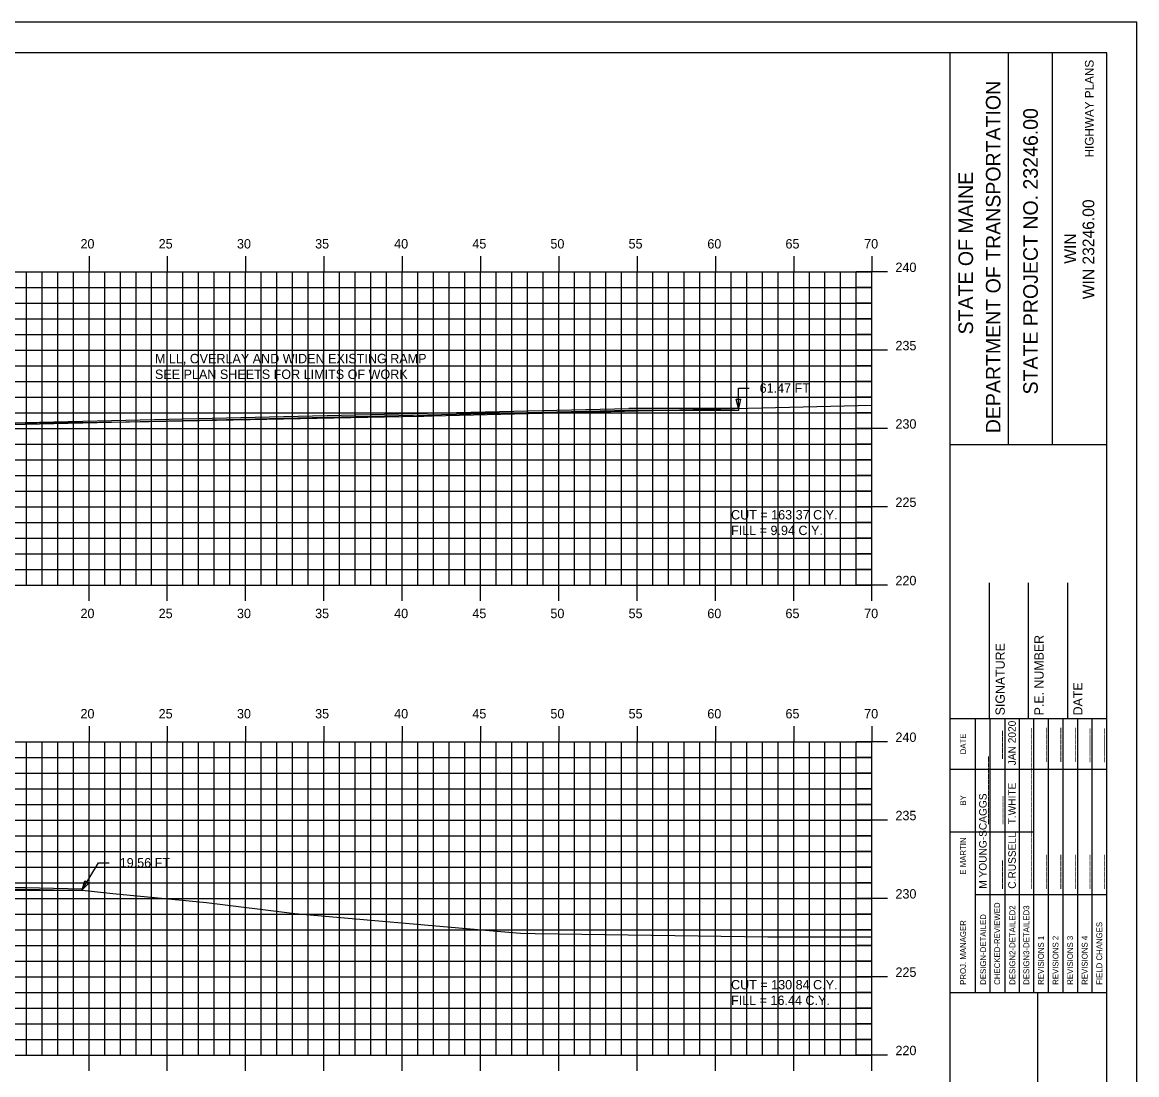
# Model space of a CAD drawing. Extents: x 1136989 to 1137159, y 608981 to 609091.
# Drawn here: x 1137087.9 to 1137159, y 609024.1 to 609091.3 of the extents above; entities that cross this region are included whole.
import ezdxf

# ---------------------------------------------------------------- set-up
doc = ezdxf.new("R2010")
doc.units = 0
for name, color, linetype in [('ANNOTATION', 7, 'Continuous'), ('BORDER', 7, 'Continuous'), ('D_Roadway_Edge_Shoulder', 7, 'Continuous'), ('D_Text_Standard', 7, 'Continuous'), ('H_V ANNOTATION', 7, 'Continuous'), ('HIGHWAY_TITLE', 7, 'Continuous'), ('MAJOR', 7, 'Continuous'), ('MINOR', 7, 'Continuous'), ('PLOT BOUNDARY', 7, 'Continuous'), ('S_Roadway_Centerline', 7, 'Continuous')]:
    doc.layers.add(name, color=color, linetype=linetype)

msp = doc.modelspace()

# ---------------------------------------------------------------- linework, layer by layer
at = {"layer": 'BORDER'}
for p, q in [((1137147.14, 608984.335), (1137147.14, 609089.335)), ((1137150.869, 609064.332), (1137150.869, 609089.332)), ((1137153.664, 609064.332), (1137153.664, 609089.332)), ((1137147.141, 609064.329), (1137157.14, 609064.329)), ((1137149.64, 609046.838), (1137149.64, 609055.485)), ((1137152.14, 609046.838), (1137152.14, 609055.485)), ((1137154.64, 609046.838), (1137154.64, 609055.485)), ((1137147.14, 609046.838), (1137157.14, 609046.838)), ((1137147.14, 609029.338), (1137157.14, 609029.338)), ((1137152.731, 608994.338), (1137152.731, 609029.338))]:
    msp.add_line(p, q, dxfattribs=at)
msp.add_lwpolyline([(1136997.14, 608984.335), (1137157.14, 608984.335), (1137157.14, 609089.335), (1136997.14, 609089.335)], close=True, dxfattribs=at)
for points in [[(1137148.755, 609043.588), (1137148.755, 609046.838)], [(1137149.687, 609029.341), (1137149.687, 609046.838)], [(1137150.619, 609046.838), (1137150.619, 609029.341)], [(1137151.551, 609029.341), (1137151.551, 609046.838)], [(1137152.482, 609029.341), (1137152.482, 609046.838)], [(1137153.414, 609029.341), (1137153.414, 609046.838)], [(1137154.346, 609029.341), (1137154.346, 609046.838)], [(1137155.278, 609029.341), (1137155.278, 609046.838)], [(1137156.209, 609029.341), (1137156.209, 609046.838)], [(1137148.756, 609029.341), (1137148.756, 609046.132)], [(1137147.14, 609043.588), (1137157.14, 609043.588)], [(1137147.14, 609039.588), (1137148.756, 609039.588)], [(1137148.755, 609039.588), (1137152.482, 609039.588)], [(1137148.755, 609035.588), (1137157.14, 609035.588)]]:
    msp.add_lwpolyline(points, dxfattribs=at)
at = {"layer": 'D_Roadway_Edge_Shoulder'}
for p in [(1137087.14, 609065.695), (1137133.61, 609066.625)]:
    msp.add_line(p, (1137126.61, 609066.625), dxfattribs=at)
for points in [[(1137133.61, 609066.625), (1137133.61, 609066.5), (1137126.61, 609066.5), (1137087.14, 609065.57)], [(1137087.14, 609036.052), (1137091.698, 609035.961), (1137091.695, 609035.836), (1137087.14, 609035.927)]]:
    msp.add_lwpolyline(points, dxfattribs=at)
at = {"layer": 'D_Text_Standard'}
for points in [[(1137133.61, 609066.625), (1137133.607, 609067.925), (1137134.287, 609067.925)], [(1137091.697, 609035.899), (1137092.74, 609037.623), (1137093.42, 609037.623)]]:
    msp.add_lwpolyline(points, dxfattribs=at)
for points in [[(1137133.61, 609066.625), (1137133.463, 609067.207), (1137133.754, 609067.208)], [(1137091.697, 609035.899), (1137091.873, 609036.472), (1137092.122, 609036.321)]]:
    msp.add_lwpolyline(points, close=True, dxfattribs=at)
at = {"layer": 'MAJOR'}
for p, q in [((1137092.14, 609076.337), (1137092.14, 609075.335)), ((1137097.14, 609076.337), (1137097.14, 609075.335)), ((1137102.14, 609076.337), (1137102.14, 609075.335)), ((1137107.14, 609076.337), (1137107.14, 609075.335)), ((1137112.14, 609076.337), (1137112.14, 609075.335)), ((1137117.14, 609076.337), (1137117.14, 609075.335)), ((1137122.14, 609076.337), (1137122.14, 609075.335)), ((1137127.14, 609076.337), (1137127.14, 609075.335)), ((1137132.14, 609076.337), (1137132.14, 609075.335)), ((1137137.14, 609076.337), (1137137.14, 609075.335)), ((1137142.14, 609076.337), (1137142.14, 609075.335)), ((1137002.14, 609075.335), (1137142.14, 609075.335)), ((1137002.14, 609075.335), (1137142.14, 609075.335)), ((1137092.14, 609055.335), (1137092.14, 609075.335)), ((1137097.14, 609055.335), (1137097.14, 609075.335)), ((1137102.14, 609055.335), (1137102.14, 609075.335)), ((1137107.14, 609055.335), (1137107.14, 609075.335)), ((1137112.14, 609055.335), (1137112.14, 609075.335)), ((1137117.14, 609055.335), (1137117.14, 609075.335)), ((1137122.14, 609055.335), (1137122.14, 609075.335)), ((1137127.14, 609055.335), (1137127.14, 609075.335)), ((1137132.14, 609055.335), (1137132.14, 609075.335)), ((1137137.14, 609055.335), (1137137.14, 609075.335)), ((1137143.142, 609075.335), (1137141.138, 609075.335)), ((1137142.14, 609055.335), (1137142.14, 609075.335)), ((1137142.14, 609055.335), (1137142.14, 609075.335)), ((1137002.14, 609070.335), (1137142.14, 609070.335)), ((1137143.142, 609070.335), (1137141.138, 609070.335)), ((1137002.14, 609065.335), (1137142.14, 609065.335)), ((1137143.142, 609065.335), (1137141.138, 609065.335)), ((1137002.14, 609060.335), (1137142.14, 609060.335)), ((1137143.142, 609060.335), (1137141.138, 609060.335)), ((1137002.14, 609055.335), (1137142.14, 609055.335)), ((1137002.14, 609055.335), (1137142.14, 609055.335)), ((1137092.14, 609054.333), (1137092.14, 609055.335)), ((1137097.14, 609054.333), (1137097.14, 609055.335)), ((1137102.14, 609054.333), (1137102.14, 609055.335)), ((1137107.14, 609054.333), (1137107.14, 609055.335)), ((1137112.14, 609054.333), (1137112.14, 609055.335)), ((1137117.14, 609054.333), (1137117.14, 609055.335)), ((1137122.14, 609054.333), (1137122.14, 609055.335)), ((1137127.14, 609054.333), (1137127.14, 609055.335)), ((1137132.14, 609054.333), (1137132.14, 609055.335)), ((1137137.14, 609054.333), (1137137.14, 609055.335)), ((1137143.142, 609055.335), (1137141.138, 609055.335)), ((1137142.14, 609054.333), (1137142.14, 609055.335)), ((1137092.14, 609046.337), (1137092.14, 609045.335)), ((1137097.14, 609046.337), (1137097.14, 609045.335)), ((1137102.14, 609046.337), (1137102.14, 609045.335)), ((1137107.14, 609046.337), (1137107.14, 609045.335)), ((1137112.14, 609046.337), (1137112.14, 609045.335)), ((1137117.14, 609046.337), (1137117.14, 609045.335)), ((1137122.14, 609046.337), (1137122.14, 609045.335)), ((1137127.14, 609046.337), (1137127.14, 609045.335)), ((1137132.14, 609046.337), (1137132.14, 609045.335)), ((1137137.14, 609046.337), (1137137.14, 609045.335)), ((1137142.14, 609046.337), (1137142.14, 609045.335)), ((1137002.14, 609045.335), (1137142.14, 609045.335)), ((1137002.14, 609045.335), (1137142.14, 609045.335)), ((1137092.14, 609025.335), (1137092.14, 609045.335)), ((1137097.14, 609025.335), (1137097.14, 609045.335)), ((1137102.14, 609025.335), (1137102.14, 609045.335)), ((1137107.14, 609025.335), (1137107.14, 609045.335)), ((1137112.14, 609025.335), (1137112.14, 609045.335)), ((1137117.14, 609025.335), (1137117.14, 609045.335)), ((1137122.14, 609025.335), (1137122.14, 609045.335)), ((1137127.14, 609025.335), (1137127.14, 609045.335)), ((1137132.14, 609025.335), (1137132.14, 609045.335)), ((1137137.14, 609025.335), (1137137.14, 609045.335)), ((1137143.142, 609045.335), (1137141.138, 609045.335)), ((1137142.14, 609025.335), (1137142.14, 609045.335)), ((1137142.14, 609025.335), (1137142.14, 609045.335)), ((1137002.14, 609040.335), (1137142.14, 609040.335)), ((1137143.142, 609040.335), (1137141.138, 609040.335)), ((1137002.14, 609035.335), (1137142.14, 609035.335)), ((1137143.142, 609035.335), (1137141.138, 609035.335)), ((1137002.14, 609030.335), (1137142.14, 609030.335)), ((1137143.142, 609030.335), (1137141.138, 609030.335)), ((1137002.14, 609025.335), (1137142.14, 609025.335)), ((1137002.14, 609025.335), (1137142.14, 609025.335)), ((1137092.14, 609024.333), (1137092.14, 609025.335)), ((1137097.14, 609024.333), (1137097.14, 609025.335)), ((1137102.14, 609024.333), (1137102.14, 609025.335)), ((1137107.14, 609024.333), (1137107.14, 609025.335)), ((1137112.14, 609024.333), (1137112.14, 609025.335)), ((1137117.14, 609024.333), (1137117.14, 609025.335)), ((1137122.14, 609024.333), (1137122.14, 609025.335)), ((1137127.14, 609024.333), (1137127.14, 609025.335)), ((1137132.14, 609024.333), (1137132.14, 609025.335)), ((1137137.14, 609024.333), (1137137.14, 609025.335)), ((1137143.142, 609025.335), (1137141.138, 609025.335)), ((1137142.14, 609024.333), (1137142.14, 609025.335))]:
    msp.add_line(p, q, dxfattribs=at)
at = {"layer": 'MINOR'}
for p, q in [((1137088.14, 609055.335), (1137088.14, 609075.335)), ((1137089.14, 609055.335), (1137089.14, 609075.335)), ((1137090.14, 609055.335), (1137090.14, 609075.335)), ((1137091.14, 609055.335), (1137091.14, 609075.335)), ((1137093.14, 609055.335), (1137093.14, 609075.335)), ((1137094.14, 609055.335), (1137094.14, 609075.335)), ((1137095.14, 609055.335), (1137095.14, 609075.335)), ((1137096.14, 609055.335), (1137096.14, 609075.335)), ((1137098.14, 609055.335), (1137098.14, 609075.335)), ((1137099.14, 609055.335), (1137099.14, 609075.335)), ((1137100.14, 609055.335), (1137100.14, 609075.335)), ((1137101.14, 609055.335), (1137101.14, 609075.335)), ((1137103.14, 609055.335), (1137103.14, 609075.335)), ((1137104.14, 609055.335), (1137104.14, 609075.335)), ((1137105.14, 609055.335), (1137105.14, 609075.335)), ((1137106.14, 609055.335), (1137106.14, 609075.335)), ((1137108.14, 609055.335), (1137108.14, 609075.335)), ((1137109.14, 609055.335), (1137109.14, 609075.335)), ((1137110.14, 609055.335), (1137110.14, 609075.335)), ((1137111.14, 609055.335), (1137111.14, 609075.335)), ((1137113.14, 609055.335), (1137113.14, 609075.335)), ((1137114.14, 609055.335), (1137114.14, 609075.335)), ((1137115.14, 609055.335), (1137115.14, 609075.335)), ((1137116.14, 609055.335), (1137116.14, 609075.335)), ((1137118.14, 609055.335), (1137118.14, 609075.335)), ((1137119.14, 609055.335), (1137119.14, 609075.335)), ((1137120.14, 609055.335), (1137120.14, 609075.335)), ((1137121.14, 609055.335), (1137121.14, 609075.335)), ((1137123.14, 609055.335), (1137123.14, 609075.335)), ((1137124.14, 609055.335), (1137124.14, 609075.335)), ((1137125.14, 609055.335), (1137125.14, 609075.335)), ((1137126.14, 609055.335), (1137126.14, 609075.335)), ((1137128.14, 609055.335), (1137128.14, 609075.335)), ((1137129.14, 609055.335), (1137129.14, 609075.335)), ((1137130.14, 609055.335), (1137130.14, 609075.335)), ((1137131.14, 609055.335), (1137131.14, 609075.335)), ((1137133.14, 609055.335), (1137133.14, 609075.335)), ((1137134.14, 609055.335), (1137134.14, 609075.335)), ((1137135.14, 609055.335), (1137135.14, 609075.335)), ((1137136.14, 609055.335), (1137136.14, 609075.335)), ((1137138.14, 609055.335), (1137138.14, 609075.335)), ((1137139.14, 609055.335), (1137139.14, 609075.335)), ((1137140.14, 609055.335), (1137140.14, 609075.335)), ((1137141.14, 609055.335), (1137141.14, 609075.335)), ((1137002.14, 609074.335), (1137142.14, 609074.335)), ((1137142.14, 609074.335), (1137141.138, 609074.335)), ((1137002.14, 609073.335), (1137142.14, 609073.335)), ((1137142.14, 609073.335), (1137141.138, 609073.335)), ((1137002.14, 609072.335), (1137142.14, 609072.335)), ((1137142.14, 609072.335), (1137141.138, 609072.335)), ((1137002.14, 609071.335), (1137142.14, 609071.335)), ((1137142.14, 609071.335), (1137141.138, 609071.335)), ((1137002.14, 609069.335), (1137142.14, 609069.335)), ((1137142.14, 609069.335), (1137141.138, 609069.335)), ((1137002.14, 609068.335), (1137142.14, 609068.335)), ((1137142.14, 609068.335), (1137141.138, 609068.335)), ((1137002.14, 609067.335), (1137142.14, 609067.335)), ((1137142.14, 609067.335), (1137141.138, 609067.335)), ((1137002.14, 609066.335), (1137142.14, 609066.335)), ((1137142.14, 609066.335), (1137141.138, 609066.335)), ((1137002.14, 609064.335), (1137142.14, 609064.335)), ((1137142.14, 609064.335), (1137141.138, 609064.335)), ((1137002.14, 609063.335), (1137142.14, 609063.335)), ((1137142.14, 609063.335), (1137141.138, 609063.335)), ((1137002.14, 609062.335), (1137142.14, 609062.335)), ((1137142.14, 609062.335), (1137141.138, 609062.335)), ((1137002.14, 609061.335), (1137142.14, 609061.335)), ((1137142.14, 609061.335), (1137141.138, 609061.335)), ((1137002.14, 609059.335), (1137142.14, 609059.335)), ((1137142.14, 609059.335), (1137141.138, 609059.335)), ((1137002.14, 609058.335), (1137142.14, 609058.335)), ((1137142.14, 609058.335), (1137141.138, 609058.335)), ((1137002.14, 609057.335), (1137142.14, 609057.335)), ((1137142.14, 609057.335), (1137141.138, 609057.335)), ((1137002.14, 609056.335), (1137142.14, 609056.335)), ((1137142.14, 609056.335), (1137141.138, 609056.335)), ((1137088.14, 609025.335), (1137088.14, 609045.335)), ((1137089.14, 609025.335), (1137089.14, 609045.335)), ((1137090.14, 609025.335), (1137090.14, 609045.335)), ((1137091.14, 609025.335), (1137091.14, 609045.335)), ((1137093.14, 609025.335), (1137093.14, 609045.335)), ((1137094.14, 609025.335), (1137094.14, 609045.335)), ((1137095.14, 609025.335), (1137095.14, 609045.335)), ((1137096.14, 609025.335), (1137096.14, 609045.335)), ((1137098.14, 609025.335), (1137098.14, 609045.335)), ((1137099.14, 609025.335), (1137099.14, 609045.335)), ((1137100.14, 609025.335), (1137100.14, 609045.335)), ((1137101.14, 609025.335), (1137101.14, 609045.335)), ((1137103.14, 609025.335), (1137103.14, 609045.335)), ((1137104.14, 609025.335), (1137104.14, 609045.335)), ((1137105.14, 609025.335), (1137105.14, 609045.335)), ((1137106.14, 609025.335), (1137106.14, 609045.335)), ((1137108.14, 609025.335), (1137108.14, 609045.335)), ((1137109.14, 609025.335), (1137109.14, 609045.335)), ((1137110.14, 609025.335), (1137110.14, 609045.335)), ((1137111.14, 609025.335), (1137111.14, 609045.335)), ((1137113.14, 609025.335), (1137113.14, 609045.335)), ((1137114.14, 609025.335), (1137114.14, 609045.335)), ((1137115.14, 609025.335), (1137115.14, 609045.335)), ((1137116.14, 609025.335), (1137116.14, 609045.335)), ((1137118.14, 609025.335), (1137118.14, 609045.335)), ((1137119.14, 609025.335), (1137119.14, 609045.335)), ((1137120.14, 609025.335), (1137120.14, 609045.335)), ((1137121.14, 609025.335), (1137121.14, 609045.335)), ((1137123.14, 609025.335), (1137123.14, 609045.335)), ((1137124.14, 609025.335), (1137124.14, 609045.335)), ((1137125.14, 609025.335), (1137125.14, 609045.335)), ((1137126.14, 609025.335), (1137126.14, 609045.335)), ((1137128.14, 609025.335), (1137128.14, 609045.335)), ((1137129.14, 609025.335), (1137129.14, 609045.335)), ((1137130.14, 609025.335), (1137130.14, 609045.335)), ((1137131.14, 609025.335), (1137131.14, 609045.335)), ((1137133.14, 609025.335), (1137133.14, 609045.335)), ((1137134.14, 609025.335), (1137134.14, 609045.335)), ((1137135.14, 609025.335), (1137135.14, 609045.335)), ((1137136.14, 609025.335), (1137136.14, 609045.335)), ((1137138.14, 609025.335), (1137138.14, 609045.335)), ((1137139.14, 609025.335), (1137139.14, 609045.335)), ((1137140.14, 609025.335), (1137140.14, 609045.335)), ((1137141.14, 609025.335), (1137141.14, 609045.335)), ((1137002.14, 609044.335), (1137142.14, 609044.335)), ((1137142.14, 609044.335), (1137141.138, 609044.335)), ((1137002.14, 609043.335), (1137142.14, 609043.335)), ((1137142.14, 609043.335), (1137141.138, 609043.335)), ((1137002.14, 609042.335), (1137142.14, 609042.335)), ((1137142.14, 609042.335), (1137141.138, 609042.335)), ((1137002.14, 609041.335), (1137142.14, 609041.335)), ((1137142.14, 609041.335), (1137141.138, 609041.335)), ((1137002.14, 609039.335), (1137142.14, 609039.335)), ((1137142.14, 609039.335), (1137141.138, 609039.335)), ((1137002.14, 609038.335), (1137142.14, 609038.335)), ((1137142.14, 609038.335), (1137141.138, 609038.335)), ((1137002.14, 609037.335), (1137142.14, 609037.335)), ((1137142.14, 609037.335), (1137141.138, 609037.335)), ((1137002.14, 609036.335), (1137142.14, 609036.335)), ((1137142.14, 609036.335), (1137141.138, 609036.335)), ((1137002.14, 609034.335), (1137142.14, 609034.335)), ((1137142.14, 609034.335), (1137141.138, 609034.335)), ((1137002.14, 609033.335), (1137142.14, 609033.335)), ((1137142.14, 609033.335), (1137141.138, 609033.335)), ((1137002.14, 609032.335), (1137142.14, 609032.335)), ((1137142.14, 609032.335), (1137141.138, 609032.335)), ((1137002.14, 609031.335), (1137142.14, 609031.335)), ((1137142.14, 609031.335), (1137141.138, 609031.335)), ((1137002.14, 609029.335), (1137142.14, 609029.335)), ((1137142.14, 609029.335), (1137141.138, 609029.335)), ((1137002.14, 609028.335), (1137142.14, 609028.335)), ((1137142.14, 609028.335), (1137141.138, 609028.335)), ((1137002.14, 609027.335), (1137142.14, 609027.335)), ((1137142.14, 609027.335), (1137141.138, 609027.335)), ((1137002.14, 609026.335), (1137142.14, 609026.335)), ((1137142.14, 609026.335), (1137141.138, 609026.335))]:
    msp.add_line(p, q, dxfattribs=at)
at = {"layer": 'PLOT BOUNDARY'}
msp.add_lwpolyline([(1136989.047, 608981.276), (1137159.047, 608981.276), (1137159.047, 609091.276), (1136989.047, 609091.276)], close=True, dxfattribs=at)
at = {"layer": 'S_Roadway_Centerline'}
for points in [[(1137002.14, 609065.362), (1137008.088, 609065.421), (1137013.376, 609065.363), (1137030.013, 609065.134), (1137036.636, 609064.798), (1137048.284, 609064.337), (1137055.773, 609064.114), (1137057.687, 609063.955), (1137059.915, 609064.293), (1137062.94, 609064.669), (1137063.163, 609064.709), (1137071.848, 609065.191), (1137074.524, 609065.325), (1137084.091, 609065.627), (1137084.658, 609065.643), (1137088.834, 609065.696), (1137094.726, 609065.766), (1137095.971, 609065.787), (1137113.166, 609066.129), (1137113.321, 609066.132), (1137113.518, 609066.138), (1137113.761, 609066.144), (1137114.049, 609066.152), (1137142.14, 609066.832)], [(1137085.691, 609035.878), (1137089.945, 609035.87), (1137091.696, 609035.872), (1137093.656, 609035.658), (1137099.635, 609035.074), (1137105.282, 609034.385), (1137117.956, 609033.269), (1137119.688, 609033.131), (1137120.629, 609033.095), (1137135.497, 609032.881), (1137142.14, 609032.887)]]:
    msp.add_lwpolyline(points, dxfattribs=at)

# ---------------------------------------------------------------- texts
at = {"layer": 'ANNOTATION'}
for s, p in [('MILL, OVERLAY AND WIDEN EXISTING RAMP', (1137096.35, 609069.508)), ('SEE PLAN SHEETS FOR LIMITS OF WORK', (1137096.35, 609068.506))]:
    msp.add_text(s, height=0.6, dxfattribs=at).set_placement(p)
at = {"layer": 'BORDER'}
for s, height, p in [('DEPARTMENT OF TRANSPORTATION', 0.93176, (1137150.347, 609065.041)), ('STATE PROJECT NO. 23246.00', 0.93176, (1137152.732, 609067.517)), ('STATE OF MAINE', 0.93176, (1137148.595, 609071.347)), ('WIN 23246.00', 0.74527, (1137156.336, 609073.596)), ('WIN', 0.7453, (1137155.177, 609075.865)), ('P.E. NUMBER', 0.59055, (1137153.101, 609047.03)), ('SIGNATURE', 0.5906, (1137150.62, 609047.03)), ('DATE', 0.5906, (1137155.581, 609047.03)), ('JAN 2020', 0.4845, (1137151.326, 609043.843)), ('DATE', 0.3714, (1137148.144, 609044.544)), ('_____', 0.4845, (1137150.357, 609044.243)), ('______', 0.4845, (1137152.221, 609044.063)), ('______', 0.4845, (1137153.152, 609044.065)), ('______', 0.4845, (1137154.084, 609044.067)), ('______', 0.4845, (1137155.016, 609044.067)), ('______', 0.4845, (1137155.947, 609044.036)), ('______', 0.4845, (1137156.879, 609044.036)), ('____________', 0.48455, (1137149.463, 609040.073)), ('____________', 0.48455, (1137152.221, 609040.073)), ('T.WHITE', 0.4845, (1137151.326, 609040.073)), ('M YOUNG-SCAGGS', 0.48455, (1137149.463, 609035.961)), ('BY', 0.3714, (1137148.144, 609041.273)), ('_____', 0.4845, (1137150.395, 609040.073)), ('____________', 0.48455, (1137152.221, 609035.961)), ('E MARTIN', 0.3727, (1137148.144, 609036.855)), ('C.RUSSELL', 0.4845, (1137151.326, 609035.961)), ('_____', 0.4845, (1137150.357, 609035.961)), ('______', 0.4845, (1137153.152, 609035.961)), ('______', 0.4845, (1137154.084, 609035.961)), ('______', 0.4845, (1137155.016, 609035.961)), ('______', 0.4845, (1137155.947, 609035.961)), ('______', 0.4845, (1137156.879, 609035.961)), ('CHECKED-REVIEWED', 0.37275, (1137150.321, 609029.826)), ('DESIGN3-DETAILED3', 0.37275, (1137152.184, 609029.826)), ('DESIGN-DETAILED', 0.37275, (1137149.427, 609029.826)), ('DESIGN2-DETAILED2', 0.37275, (1137151.29, 609029.826)), ('PROJ. MANAGER', 0.37275, (1137148.144, 609029.826)), ('FIELD CHANGES', 0.37275, (1137156.843, 609029.826)), ('REVISIONS 1', 0.37275, (1137153.116, 609029.826)), ('REVISIONS 2', 0.37275, (1137154.048, 609029.826)), ('REVISIONS 3', 0.37275, (1137154.979, 609029.826)), ('REVISIONS 4', 0.37275, (1137155.911, 609029.826))]:
    msp.add_text(s, height=height, rotation=90, dxfattribs=at).set_placement(p)
at = {"layer": 'D_Text_Standard'}
for s, p in [('61.47 FT', (1137134.967, 609067.625)), ('CUT = 163.37 C.Y.', (1137133.14, 609059.535)), ('FILL = 9.94 C.Y.', (1137133.14, 609058.539)), ('19.56 FT', (1137094.1, 609037.323)), ('CUT = 130.84 C.Y.', (1137133.14, 609029.535)), ('FILL = 16.44 C.Y.', (1137133.14, 609028.539))]:
    msp.add_text(s, height=0.6, dxfattribs=at).set_placement(p)
at = {"layer": 'H_V ANNOTATION'}
for s, p in [('20', (1137091.594, 609076.835)), ('25', (1137096.586, 609076.835)), ('30', (1137101.588, 609076.835)), ('35', (1137106.58, 609076.835)), ('40', (1137111.626, 609076.835)), ('45', (1137116.618, 609076.835)), ('50', (1137121.604, 609076.835)), ('55', (1137126.596, 609076.835)), ('60', (1137131.626, 609076.835)), ('65', (1137136.618, 609076.835)), ('70', (1137141.642, 609076.835)), ('240', (1137143.64, 609075.335)), ('235', (1137143.64, 609070.335)), ('230', (1137143.64, 609065.335)), ('225', (1137143.64, 609060.335)), ('220', (1137143.64, 609055.335)), ('20', (1137091.594, 609053.235)), ('25', (1137096.586, 609053.235)), ('30', (1137101.588, 609053.235)), ('35', (1137106.58, 609053.235)), ('40', (1137111.626, 609053.235)), ('45', (1137116.618, 609053.235)), ('50', (1137121.604, 609053.235)), ('55', (1137126.596, 609053.235)), ('60', (1137131.626, 609053.235)), ('65', (1137136.618, 609053.235)), ('70', (1137141.642, 609053.235)), ('20', (1137091.594, 609046.835)), ('25', (1137096.586, 609046.835)), ('30', (1137101.588, 609046.835)), ('35', (1137106.58, 609046.835)), ('40', (1137111.626, 609046.835)), ('45', (1137116.618, 609046.835)), ('50', (1137121.604, 609046.835)), ('55', (1137126.596, 609046.835)), ('60', (1137131.626, 609046.835)), ('65', (1137136.618, 609046.835)), ('70', (1137141.642, 609046.835)), ('240', (1137143.64, 609045.335)), ('235', (1137143.64, 609040.335)), ('230', (1137143.64, 609035.335)), ('225', (1137143.64, 609030.335)), ('220', (1137143.64, 609025.335))]:
    msp.add_text(s, height=0.6, dxfattribs=at).set_placement(p)
at = {"layer": 'HIGHWAY_TITLE'}
msp.add_text('HIGHWAY PLANS', height=0.55901, rotation=90, dxfattribs=at).set_placement((1137156.298, 609082.65))

doc.saveas('drawing.dxf')
